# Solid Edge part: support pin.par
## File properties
Author: Robert a Rhodes jr
Template: NORMENG.PAR
Last saved by: CADCIM
Revision: 2
Application: Solid Edge
Density: 0 lbm/in^3
Accuracy: 0.99
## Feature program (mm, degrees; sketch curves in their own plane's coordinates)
sketch for "unnamed RevolvedProtrusion 1" plane through (0, 0, 0) normal (0, -1, 0) x-axis (1, 0, 0)
  line (0, 29.8952) -> (2.413, 29.8952)
  line (2.413, 29.8952) -> (2.413, 17.1952)
  line (2.413, 17.1952) -> (3.175, 17.1952)
  line (3.175, 17.1952) -> (3.175, -24.0798)
  line (3.175, -24.0798) -> (2.413, -24.0798)
  line (2.413, -24.0798) -> (2.413, -36.7798)
  line (2.413, -36.7798) -> (0, -36.7798)
  line (0, -36.7798) -> (0, 29.8952)
revolve "unnamed RevolvedProtrusion 1" add finite 360 deg
chamfer "unnamed Chamfer 1"
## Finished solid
Body 1: solid body, 9 faces, 8 edges, 0 vertices.
  Faces by surface: plane 4, cylinder 3, cone 2
  Edges by curve: circle 8
Bounding box of the edges (mm): 6.350 x 6.350 x 66.675, from (-3.175, -3.175, -36.7798) to (3.175, 3.175, 29.8952).
Cylindrical faces by radius (mm): R2.413 x2, R3.175 x1
Conical faces (half-angle, radius in mm at the cone's reference point): 45 deg R2.159 x1, 45 deg R2.413 x1
Planar faces by outward normal: +z 2, -z 2
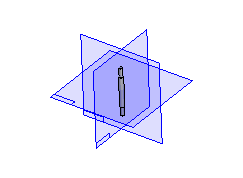
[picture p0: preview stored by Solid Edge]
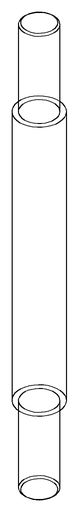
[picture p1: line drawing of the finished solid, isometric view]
